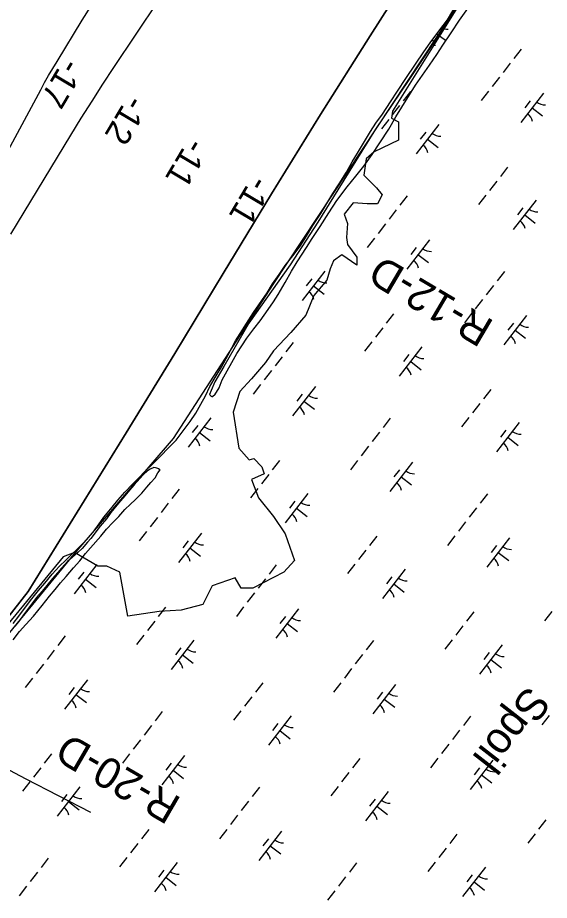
# Model space of a CAD drawing. Extents: x 3888273 to 3909528, y 158682 to 181032.
# Drawn here: x 3901510 to 3902228, y 169134 to 170326 of the extents above; entities that cross this region are included whole.
import ezdxf

# ---------------------------------------------------------------- set-up
doc = ezdxf.new("R2010")
doc.units = 0
for name, color, linetype in [('V-CHAN-SPOL', 7, 'Continuous'), ('V-LEVE-TOET', 7, 'Continuous'), ('V-RIVR-EDGE', 7, 'Continuous'), ('V-RIVR-JETY', 7, 'Continuous'), ('V-RIVR-RANG', 7, 'Continuous'), ('V-RIVR-RANG-IDEN', 7, 'Continuous'), ('V-RRAP-FSHR', 7, 'Continuous'), ('V-TOPO-DPTH', 7, 'Continuous'), ('V-TOPO-MINR', 7, 'Continuous'), ('V-WETL-SWMP', 7, 'Continuous')]:
    doc.layers.add(name, color=color, linetype=linetype)

msp = doc.modelspace()

# ---------------------------------------------------------------- linework, layer by layer
at = {"layer": 'V-LEVE-TOET'}
msp.add_lwpolyline([(3901608.3, 169252.6), (3901521, 169297.6), (3901468.7, 169325), (3901399.6, 169361.3), (3901370.6, 169378.6), (3901358, 169391.3)], dxfattribs=at)
at = {"layer": 'V-RIVR-EDGE'}
msp.add_lwpolyline([(3902103.9, 170339.9), (3902016.4, 170199.2), (3902014.9, 170189.8), (3902024.2, 170185.1), (3902024.2, 170160.1), (3901991.4, 170144.5), (3901980.5, 170135.1), (3901977.3, 170113.2), (3901994.5, 170096), (3902002.3, 170086.6), (3901996.1, 170074.1), (3901982, 170074.1), (3901963.3, 170075.7), (3901950.8, 170060.1), (3901955.5, 170047.6), (3901953.9, 170028.8), (3901955.5, 170019.4), (3901968, 170002.2), (3901968, 169991.3), (3901947.6, 170005.4), (3901936.7, 169997.5), (3901932, 169986.6), (3901927.3, 169971), (3901910.1, 169950.6), (3901899.2, 169924.1), (3901878.9, 169900.6), (3901855.4, 169875.6), (3901844.5, 169860), (3901825.7, 169838.1), (3901810.1, 169820.9), (3901800.7, 169792.8), (3901808.5, 169744.3), (3901822.6, 169728.7), (3901828.8, 169730.2), (3901839.8, 169719.3), (3901842.9, 169709.9), (3901825.7, 169702.1), (3901835.1, 169677.1), (3901855.4, 169652.1), (3901871, 169628.6), (3901883.6, 169592.7), (3901869.5, 169577.1), (3901827.3, 169555.2), (3901811.6, 169555.2), (3901803.8, 169569.3), (3901772.6, 169558.3), (3901760.1, 169533.3), (3901730.4, 169525.5), (3901700.7, 169523.9), (3901658.5, 169517.7), (3901647.5, 169577.1), (3901630.3, 169584.9), (3901617.8, 169584.9), (3901586.6, 169603.6), (3901570.9, 169597.4), (3901397.4, 169386.4)], dxfattribs=at)
at = {"layer": 'V-RIVR-JETY'}
for points in [[(3902102, 170336.8), (3902038.2, 170241.9), (3901993.1, 170175), (3901966.5, 170132.2), (3901942.3, 170093.4), (3901915.3, 170049.3), (3901877.7, 169991.7), (3901822.1, 169913.1), (3901788.1, 169854.7), (3901776, 169833.9)], [(3901785.9, 169836.8), (3901805.8, 169872.4), (3901819.5, 169892.8), (3901828.9, 169905.3), (3901837.6, 169916.1), (3901848.1, 169931.7), (3901855.2, 169942.1), (3901861.5, 169951.7), (3901871.2, 169968.1), (3901879.8, 169983.3), (3901887.2, 169995.8), (3901900.2, 170015.4), (3901907.6, 170027.4), (3901918.6, 170043.8), (3901930.3, 170062.2), (3901940.9, 170078.6), (3901955, 170097.1), (3901966.8, 170111.5), (3901977.3, 170125.1), (3901988.7, 170140.8), (3901999.3, 170156.8), (3902011.4, 170175.2), (3902020.8, 170191.6), (3902047.4, 170234.4), (3902066.2, 170261.3), (3902076, 170276.1), (3902084.2, 170288.5), (3902095.6, 170305.3), (3902106.9, 170322.2), (3902117.9, 170338.2)], [(3901776, 169833.9), (3901771, 169822.3), (3901769, 169816.8), (3901770.6, 169814.8), (3901770.6, 169814.4), (3901772.2, 169814), (3901773, 169814), (3901776.6, 169817.2), (3901778.5, 169820), (3901782, 169826), (3901785.9, 169836.8)], [(3901503.6, 169485.7), (3901512.2, 169496.9), (3901520.5, 169506.2), (3901531.1, 169517.4), (3901542.9, 169531.9), (3901552.7, 169544.3), (3901560.5, 169553.5), (3901567.6, 169562.3), (3901575.1, 169571.2), (3901584.9, 169582.8), (3901593.5, 169592.4), (3901601.4, 169602.1), (3901608.1, 169609.7), (3901621.8, 169625.7), (3901629.7, 169635), (3901638.3, 169644.2), (3901646.2, 169652.2), (3901654.4, 169661.5), (3901662.3, 169668.7), (3901668.6, 169674.7), (3901677.3, 169683.6), (3901684.3, 169691.6), (3901689.4, 169698), (3901695.3, 169704.5), (3901699.2, 169710.9), (3901702, 169714.9), (3901702, 169714.9), (3901700.8, 169715.6), (3901700.8, 169716.4), (3901699.2, 169716.8), (3901697.6, 169717.2), (3901696, 169717.6), (3901693.6, 169718.4), (3901688.5, 169715.9), (3901684.9, 169713.9), (3901679.8, 169708.7), (3901674.7, 169703.4), (3901667.2, 169695), (3901660.9, 169687.8), (3901654.6, 169679.8), (3901646, 169670.1), (3901635.4, 169657.7), (3901629.5, 169648.9), (3901621.3, 169638.9), (3901608.7, 169622.4), (3901604, 169617.2), (3901596.9, 169608.8), (3901591, 169603.5), (3901583.5, 169597.1), (3901576.8, 169591.1), (3901569, 169582.2), (3901563.9, 169576.6), (3901556.8, 169568.2), (3901548.9, 169559), (3901542.7, 169551.3), (3901535.2, 169542.5), (3901526.9, 169532.1), (3901518.7, 169520.9), (3901510.9, 169510), (3901506.2, 169504.4)]]:
    msp.add_lwpolyline(points, dxfattribs=at)
at = {"layer": 'V-RRAP-FSHR'}
msp.add_lwpolyline([(3899996.7, 166588.8), (3900029.7, 166643.4), (3900051.8, 166695.8), (3900145, 166878), (3900473, 167514.6), (3900528.8, 167603.3), (3900571.9, 167693.2), (3900769.5, 168220.1), (3900854, 168410.1), (3901111.7, 168921.3), (3901230.8, 169130.1), (3901232.3, 169133), (3901298.6, 169231.8), (3901395, 169369.5), (3901586, 169601.1), (3901720.2, 169757.4), (3901855.1, 169965.2), (3902076, 170299.4), (3902258.6, 170576), (3902394.3, 170771.7), (3902466.4, 170877.4)], dxfattribs=at)
at = {"layer": 'V-TOPO-DPTH'}
for points in [[(3902745.9, 171376.6), (3902701.4, 171321.5), (3902669.5, 171281.6), (3902638.1, 171241.4), (3902607.1, 171200.8), (3902576.5, 171159.9), (3902314.2, 170804.4), (3902294.8, 170777.6), (3902275.9, 170750.7), (3902257.4, 170723.3), (3902239.3, 170695.8), (3902053.6, 170407.4), (3901985.9, 170301.2), (3901918.9, 170194.7), (3901852.7, 170087.6), (3901787.2, 169980.1), (3901721.9, 169872.4), (3901656.3, 169765), (3901590.2, 169657.8), (3901523.7, 169550.8), (3901139.1, 169059.9)], [(3901467.8, 170093.5), (3901540.7, 170228.2), (3901546, 170237.9), (3901551.5, 170247.5), (3901557.1, 170257.1), (3901562.8, 170266.6), (3901597, 170322.5), (3901620.1, 170359.8)], [(3901467.8, 170093.5), (3901540.7, 170228.2), (3901546, 170237.9), (3901551.5, 170247.5), (3901557.1, 170257.1), (3901562.8, 170266.6), (3901597, 170322.5), (3901620.1, 170359.8)]]:
    msp.add_lwpolyline(points, dxfattribs=at)
at = {"layer": 'V-TOPO-MINR'}
for points in [[(3901500.4, 170033.5), (3901581.3, 170166.8), (3901595.6, 170189.9), (3901610.1, 170212.9), (3901624.9, 170235.7), (3901639.8, 170258.4), (3901700, 170348.3), (3901745, 170416), (3901789.9, 170483.7), (3901834.4, 170551.7), (3901878.7, 170619.9), (3902010, 170822.7), (3902029.6, 170853.2), (3902049.2, 170883.7), (3902068.6, 170914.2), (3902088, 170944.8), (3902503.4, 171603.5), (3902912.5, 172181.4)], [(3901139.1, 169059.9), (3901523.7, 169550.8), (3901590.2, 169657.8), (3901656.3, 169765), (3901721.9, 169872.4), (3901787.2, 169980.1), (3901852.7, 170087.6), (3901918.9, 170194.7), (3901985.9, 170301.2), (3902053.6, 170407.4), (3902239.3, 170695.8), (3902257.4, 170723.3), (3902275.9, 170750.7), (3902294.8, 170777.6), (3902314.2, 170804.4), (3902576.5, 171159.9), (3902607.1, 171200.8), (3902638.1, 171241.4), (3902669.5, 171281.6), (3902701.4, 171321.5), (3902745.9, 171376.6)], [(3901467.8, 170093.5), (3901540.7, 170228.2), (3901546, 170237.9), (3901551.5, 170247.5), (3901557.1, 170257.1), (3901562.8, 170266.6), (3901597, 170322.5), (3901620.1, 170359.8)]]:
    msp.add_lwpolyline(points, dxfattribs=at)
at = {"layer": 'V-WETL-SWMP'}
for p, q in [((3902090.5, 170322.9), (3902102.4, 170342.6)), ((3902078.9, 170307.5), (3902090.5, 170322.9)), ((3902067.3, 170291.7), (3902078.9, 170307.5)), ((3902076.3, 170304), (3902087.8, 170295.1)), ((3902058.8, 170279.5), (3902067.3, 170291.7)), ((3902047.3, 170262.9), (3902058.8, 170279.5)), ((3902190.3, 170283), (3902180.4, 170270.4)), ((3902175.5, 170264.1), (3902165.7, 170251.4)), ((3902034.1, 170243.6), (3902047.3, 170262.9)), ((3902023, 170226.6), (3902034.1, 170243.6)), ((3902160.8, 170245.1), (3902151, 170232.5)), ((3902013.7, 170212.1), (3902023, 170226.6)), ((3902040.6, 170225.9), (3902030.8, 170213.3)), ((3902146, 170226.2), (3902136.2, 170213.6)), ((3902220.2, 170223.7), (3902189.5, 170184.3)), ((3902002.5, 170195.5), (3902013.7, 170212.1)), ((3902025.8, 170207), (3902016, 170194.4)), ((3902202.4, 170213.5), (3902195.1, 170204)), ((3902204.8, 170204), (3902219, 170192.9)), ((3901993.6, 170183.2), (3902002.5, 170195.5)), ((3901986.7, 170171.8), (3901993.6, 170183.2)), ((3902011.1, 170188.1), (3902001.3, 170175.4)), ((3902078.9, 170181.3), (3902048.2, 170141.8)), ((3901978.6, 170158.4), (3901986.7, 170171.8)), ((3902061.2, 170171), (3902053.8, 170161.5)), ((3901969, 170142.6), (3901978.6, 170158.4)), ((3902063.6, 170161.5), (3902077.8, 170150.5)), ((3901961.7, 170131.2), (3901969, 170142.6)), ((3901954, 170117), (3901961.7, 170131.2)), ((3902171.9, 170123.8), (3902162, 170111.2)), ((3901944, 170101.3), (3901954, 170117)), ((3901935.5, 170088.2), (3901944, 170101.3)), ((3902157.1, 170104.9), (3902147.3, 170092.2)), ((3901929, 170076.8), (3901935.5, 170088.2)), ((3902036.2, 170085), (3902026.3, 170072.3)), ((3902142.4, 170085.9), (3902132.6, 170073.3)), ((3901919.3, 170061), (3901929, 170076.8)), ((3902210.2, 170079.1), (3902179.5, 170039.7)), ((3901908.5, 170044.9), (3901919.3, 170061)), ((3902021.4, 170066), (3902011.6, 170053.4)), ((3902192.5, 170068.9), (3902185.1, 170059.4)), ((3902194.9, 170059.4), (3902209.1, 170048.3)), ((3901900.1, 170030.7), (3901908.5, 170044.9)), ((3902006.7, 170047.1), (3901996.9, 170034.4)), ((3901891.6, 170017.3), (3901900.1, 170030.7)), ((3901991.9, 170028.1), (3901982.1, 170015.5)), ((3902066.1, 170025.7), (3902035.4, 169986.2)), ((3901881.5, 170004.2), (3901891.6, 170017.3)), ((3902048.3, 170015.4), (3902041, 170005.9)), ((3901871.1, 169990.8), (3901881.5, 170004.2)), ((3902050.7, 170005.9), (3902064.9, 169994.9)), ((3901863, 169979), (3901871.1, 169990.8)), ((3901854.1, 169966.4), (3901863, 169979)), ((3901924.8, 169983.2), (3901894.1, 169943.7)), ((3902167.4, 169982.8), (3902157.6, 169970.2)), ((3901846.8, 169954.1), (3901854.1, 169966.4)), ((3901907.1, 169972.9), (3901899.7, 169963.5)), ((3901828.3, 169927.7), (3901846.8, 169954.1)), ((3901909.5, 169963.5), (3901923.7, 169952.4)), ((3902152.7, 169963.9), (3902142.9, 169951.2)), ((3902138, 169944.9), (3902128.1, 169932.3)), ((3901804, 169889.5), (3901828.3, 169927.7)), ((3902017.8, 169925.7), (3902007.9, 169913.1)), ((3902123.2, 169926), (3902113.4, 169913.4)), ((3902197.4, 169923.5), (3902166.7, 169884)), ((3902003, 169906.8), (3901993.2, 169894.2)), ((3902179.6, 169913.2), (3902172.2, 169903.8)), ((3902182, 169903.8), (3902196.2, 169892.7)), ((3901794, 169870.2), (3901804, 169889.5)), ((3901882, 169886.9), (3901872.2, 169874.3)), ((3901988.3, 169887.9), (3901978.5, 169875.2)), ((3901785.6, 169854.8), (3901794, 169870.2)), ((3902056.1, 169881.1), (3902025.4, 169841.6)), ((3902038.4, 169870.8), (3902031, 169861.3)), ((3901867.3, 169867.9), (3901857.5, 169855.3)), ((3902040.8, 169861.3), (3902055, 169850.3)), ((3901777.9, 169841.8), (3901785.6, 169854.8)), ((3901852.6, 169849), (3901842.7, 169836.4)), ((3901769.4, 169827.6), (3901777.9, 169841.8)), ((3901763.3, 169815), (3901769.4, 169827.6)), ((3901837.8, 169830.1), (3901828, 169817.4)), ((3901912, 169827.6), (3901881.3, 169788.1)), ((3902149, 169823.6), (3902139.2, 169811)), ((3901757.1, 169803.6), (3901763.3, 169815)), ((3901894.2, 169817.3), (3901886.9, 169807.9)), ((3901750.6, 169791.4), (3901757.1, 169803.6)), ((3901896.6, 169807.9), (3901910.8, 169796.8)), ((3902134.3, 169804.7), (3902124.5, 169792)), ((3901742.9, 169780.3), (3901750.6, 169791.4)), ((3901724, 169755), (3901742.9, 169780.3)), ((3901770.7, 169785.1), (3901740, 169745.7)), ((3901753, 169774.9), (3901745.6, 169765.4)), ((3902013.3, 169784.7), (3902003.5, 169772.1)), ((3902119.6, 169785.7), (3902109.7, 169773.1)), ((3902187.4, 169778.9), (3902156.7, 169739.5)), ((3901755.4, 169765.4), (3901769.6, 169754.4)), ((3901998.6, 169765.8), (3901988.8, 169753.2)), ((3902169.6, 169768.7), (3902162.3, 169759.2)), ((3901692.2, 169723.4), (3901724, 169755)), ((3902172.1, 169759.2), (3902186.3, 169748.1)), ((3901983.9, 169746.9), (3901974, 169734.2)), ((3901863.7, 169727.7), (3901853.8, 169715)), ((3901969.1, 169727.9), (3901959.3, 169715.3)), ((3901682.1, 169713.5), (3901692.2, 169723.4)), ((3902043.3, 169725.4), (3902012.6, 169686)), ((3902025.5, 169715.2), (3902018.1, 169705.7)), ((3901664.7, 169695.7), (3901672.4, 169703.2)), ((3901672.4, 169703.2), (3901682.1, 169713.5)), ((3901848.9, 169708.7), (3901839.1, 169696.1)), ((3902027.9, 169705.7), (3902042.1, 169694.7)), ((3901654.6, 169685), (3901664.7, 169695.7)), ((3901644.9, 169674.3), (3901654.6, 169685)), ((3901727.9, 169688.8), (3901718.1, 169676.2)), ((3901834.2, 169689.8), (3901824.4, 169677.2)), ((3901902, 169683), (3901871.3, 169643.5)), ((3902144.6, 169682.6), (3902134.8, 169670)), ((3901637.2, 169664.8), (3901644.9, 169674.3)), ((3901713.2, 169669.9), (3901703.4, 169657.3)), ((3901884.3, 169672.7), (3901876.9, 169663.3)), ((3901626, 169651), (3901637.2, 169664.8)), ((3901886.7, 169663.3), (3901900.9, 169652.2)), ((3902129.9, 169663.7), (3902120, 169651)), ((3901619.8, 169642.3), (3901626, 169651)), ((3901698.5, 169650.9), (3901688.6, 169638.3)), ((3902115.1, 169644.7), (3902105.3, 169632.1)), ((3901611.7, 169630.9), (3901619.8, 169642.3)), ((3901683.7, 169632), (3901673.9, 169619.4)), ((3901591.5, 169609.1), (3901602.4, 169620.2)), ((3901602.4, 169620.2), (3901611.7, 169630.9)), ((3901757.9, 169629.5), (3901727.2, 169590.1)), ((3901994.9, 169625.5), (3901985.1, 169612.9)), ((3902100.4, 169625.8), (3902090.6, 169613.1)), ((3902174.5, 169623.3), (3902143.8, 169583.8)), ((3901581.1, 169599.2), (3901591.5, 169609.1)), ((3901740.1, 169619.3), (3901732.7, 169609.8)), ((3901742.5, 169609.8), (3901756.7, 169598.7)), ((3902156.8, 169613), (3902149.4, 169603.6)), ((3901574.5, 169592.9), (3901581.1, 169599.2)), ((3901980.2, 169606.6), (3901970.4, 169594)), ((3902159.2, 169603.6), (3902173.4, 169592.5)), ((3901556.3, 169574.3), (3901566.3, 169585)), ((3901566.3, 169585), (3901574.5, 169592.9)), ((3901616.6, 169587.1), (3901585.9, 169547.6)), ((3901859.2, 169586.7), (3901849.4, 169574.1)), ((3901965.5, 169587.6), (3901955.6, 169575)), ((3901546.2, 169562), (3901556.3, 169574.3)), ((3901598.9, 169576.8), (3901591.5, 169567.3)), ((3902033.3, 169580.9), (3902002.6, 169541.4)), ((3901537.7, 169552.2), (3901546.2, 169562)), ((3901601.3, 169567.3), (3901615.5, 169556.3)), ((3901844.5, 169567.7), (3901834.7, 169555.1)), ((3902015.5, 169570.6), (3902008.2, 169561.1)), ((3902017.9, 169561.1), (3902032.2, 169550.1)), ((3901528.8, 169541.1), (3901537.7, 169552.2)), ((3901829.7, 169548.8), (3901819.9, 169536.2)), ((3901520.3, 169529.6), (3901528.8, 169541.1)), ((3901511, 169517.4), (3901520.3, 169529.6)), ((3901709.5, 169529.6), (3901699.7, 169517)), ((3901815, 169529.9), (3901805.2, 169517.2)), ((3901889.2, 169527.4), (3901858.4, 169487.9)), ((3901503.3, 169507.5), (3901511, 169517.4)), ((3901871.4, 169517.1), (3901864, 169507.7)), ((3902126.2, 169523.4), (3902116.4, 169510.8)), ((3902231.7, 169523.6), (3902221.9, 169511)), ((3901694.8, 169510.7), (3901685, 169498)), ((3901873.8, 169507.6), (3901888, 169496.6)), ((3902111.5, 169504.4), (3902101.7, 169491.8)), ((3901573.8, 169490.8), (3901564, 169478.1)), ((3901680.1, 169491.7), (3901670.2, 169479.1)), ((3901747.9, 169484.9), (3901717.2, 169445.5)), ((3901990.5, 169484.5), (3901980.7, 169471.9)), ((3902096.7, 169485.5), (3902086.9, 169472.9)), ((3902164.6, 169478.7), (3902133.9, 169439.2)), ((3901559.1, 169471.8), (3901549.3, 169459.2)), ((3901730.2, 169474.7), (3901722.8, 169465.2)), ((3901732.6, 169465.2), (3901746.8, 169454.1)), ((3901975.8, 169465.6), (3901965.9, 169453)), ((3902146.8, 169468.4), (3902139.5, 169459)), ((3901544.4, 169452.9), (3901534.5, 169440.2)), ((3902149.2, 169459), (3902163.4, 169447.9)), ((3901961, 169446.7), (3901951.2, 169434)), ((3901529.6, 169433.9), (3901519.8, 169421.3)), ((3901603.8, 169431.5), (3901573.1, 169392)), ((3901586, 169421.2), (3901578.6, 169411.7)), ((3901840.8, 169427.5), (3901831, 169414.8)), ((3901946.3, 169427.7), (3901936.5, 169415.1)), ((3902020.4, 169425.2), (3901989.7, 169385.8)), ((3901588.4, 169411.7), (3901602.6, 169400.7)), ((3901826.1, 169408.5), (3901816.3, 169395.9)), ((3902002.7, 169415), (3901995.3, 169405.5)), ((3902005.1, 169405.5), (3902019.3, 169394.5)), ((3901705.1, 169388.6), (3901695.3, 169376)), ((3901811.4, 169389.6), (3901801.5, 169377)), ((3901879.2, 169382.8), (3901848.5, 169343.3)), ((3902121.8, 169382.4), (3902112, 169369.8)), ((3902228, 169383.4), (3902218.2, 169370.7)), ((3901690.4, 169369.7), (3901680.6, 169357)), ((3901861.4, 169372.5), (3901854.1, 169363.1)), ((3901863.8, 169363.1), (3901878, 169352)), ((3902107, 169363.4), (3902097.2, 169350.8)), ((3901675.6, 169350.7), (3901665.8, 169338.1)), ((3902092.3, 169344.5), (3902082.5, 169331.9)), ((3901555.4, 169331.5), (3901545.6, 169318.9)), ((3901660.9, 169331.8), (3901651.1, 169319.2)), ((3901735, 169329.3), (3901704.3, 169289.9)), ((3901972.1, 169325.3), (3901962.3, 169312.7)), ((3902077.6, 169325.6), (3902067.7, 169312.9)), ((3902151.7, 169323.1), (3902121, 169283.6)), ((3901540.7, 169312.6), (3901530.9, 169300)), ((3901717.3, 169319.1), (3901709.9, 169309.6)), ((3901719.7, 169309.6), (3901733.9, 169298.5)), ((3902134, 169312.8), (3902126.6, 169303.4)), ((3901957.4, 169306.4), (3901947.5, 169293.8)), ((3902136.4, 169303.4), (3902150.6, 169292.3)), ((3901526, 169293.7), (3901516.1, 169281)), ((3901593.8, 169286.9), (3901563.1, 169247.4)), ((3901836.4, 169286.5), (3901826.6, 169273.8)), ((3901942.6, 169287.4), (3901932.8, 169274.8)), ((3901576, 169276.6), (3901568.7, 169267.1)), ((3902010.5, 169280.6), (3901979.8, 169241.2)), ((3901578.5, 169267.1), (3901592.7, 169256.1)), ((3901821.7, 169267.5), (3901811.8, 169254.9)), ((3901992.7, 169270.4), (3901985.3, 169260.9)), ((3901995.1, 169260.9), (3902009.3, 169249.9)), ((3901806.9, 169248.6), (3901797.1, 169236)), ((3902223.6, 169242.4), (3902213.8, 169229.7)), ((3901686.7, 169229.4), (3901676.9, 169216.8)), ((3901792.2, 169229.6), (3901782.4, 169217)), ((3901866.3, 169227.2), (3901835.6, 169187.7)), ((3901848.6, 169216.9), (3901841.2, 169207.4)), ((3902103.4, 169223.2), (3902093.6, 169210.5)), ((3902208.9, 169223.4), (3902199, 169210.8)), ((3901672, 169210.5), (3901662.2, 169197.8)), ((3901851, 169207.4), (3901865.2, 169196.4)), ((3902088.7, 169204.2), (3902078.8, 169191.6)), ((3901551, 169190.6), (3901541.2, 169177.9)), ((3901657.2, 169191.5), (3901647.4, 169178.9)), ((3901725.1, 169184.7), (3901694.4, 169145.3)), ((3901967.7, 169184.3), (3901957.9, 169171.7)), ((3902073.9, 169185.3), (3902064.1, 169172.7)), ((3902141.8, 169178.5), (3902111, 169139)), ((3901536.3, 169171.6), (3901526.4, 169159)), ((3901707.3, 169174.5), (3901700, 169165)), ((3902124, 169168.2), (3902116.6, 169158.8)), ((3901709.7, 169165), (3901723.9, 169153.9)), ((3901952.9, 169165.4), (3901943.1, 169152.8)), ((3902126.4, 169158.8), (3902140.6, 169147.7)), ((3901521.5, 169152.7), (3901511.7, 169140)), ((3901938.2, 169146.4), (3901928.4, 169133.8))]:
    msp.add_line(p, q, dxfattribs=at)
for centre, start, end in [((3902090.7, 170327.8), 242.0233, 272.8866), ((3902056.8, 170284.2), 11.343, 40.5183), ((3902222, 170225.6), 231.343, 272.8866), ((3902188.1, 170182), 11.343, 52.8866), ((3902080.7, 170183.2), 231.343, 272.8866), ((3902046.8, 170139.6), 11.343, 52.8866), ((3902212, 170081), 231.343, 272.8866), ((3902178.1, 170037.4), 11.343, 52.8866), ((3902067.9, 170027.6), 231.343, 272.8866), ((3902034, 169984), 11.343, 52.8866), ((3901926.6, 169985.1), 231.343, 272.8866), ((3901892.7, 169941.5), 11.343, 52.8866), ((3902199.2, 169925.4), 231.343, 272.8866), ((3902165.2, 169881.8), 11.343, 52.8866), ((3902057.9, 169883), 231.343, 272.8866), ((3902024, 169839.4), 11.343, 52.8866), ((3901913.8, 169829.5), 231.343, 272.8866), ((3901879.9, 169785.9), 11.343, 52.8866), ((3901772.5, 169787.1), 231.343, 272.8866), ((3902189.2, 169780.8), 231.343, 272.8866), ((3901738.6, 169743.5), 11.343, 52.8866), ((3902155.3, 169737.2), 11.343, 52.8866), ((3902045.1, 169727.4), 231.343, 272.8866), ((3902011.1, 169683.8), 11.343, 52.8866), ((3901903.8, 169684.9), 231.343, 272.8866), ((3901869.9, 169641.3), 11.343, 52.8866), ((3901759.7, 169631.4), 231.343, 272.8866), ((3902176.3, 169625.2), 231.343, 272.8866), ((3901725.7, 169587.8), 11.343, 52.8866), ((3902142.4, 169581.6), 11.343, 52.8866), ((3901618.4, 169589), 231.343, 272.8866), ((3902035.1, 169582.8), 231.343, 272.8866), ((3901584.5, 169545.4), 11.343, 52.8866), ((3902001.2, 169539.2), 11.343, 52.8866), ((3901891, 169529.3), 231.343, 272.8866), ((3901857, 169485.7), 11.343, 52.8866), ((3901749.7, 169486.9), 231.343, 272.8866), ((3902166.4, 169480.6), 231.343, 272.8866), ((3901715.8, 169443.3), 11.343, 52.8866), ((3902132.5, 169437), 11.343, 52.8866), ((3901605.6, 169433.4), 231.343, 272.8866), ((3902022.2, 169427.2), 231.343, 272.8866), ((3901571.6, 169389.8), 11.343, 52.8866), ((3901988.3, 169383.6), 11.343, 52.8866), ((3901881, 169384.7), 231.343, 272.8866), ((3901847.1, 169341.1), 11.343, 52.8866), ((3901736.8, 169331.2), 231.343, 272.8866), ((3902153.5, 169325), 231.343, 272.8866), ((3901702.9, 169287.6), 11.343, 52.8866), ((3902119.6, 169281.4), 11.343, 52.8866), ((3901595.6, 169288.8), 231.343, 272.8866), ((3902012.3, 169282.6), 231.343, 272.8866), ((3901561.7, 169245.2), 11.343, 52.8866), ((3901978.3, 169239), 11.343, 52.8866), ((3901868.1, 169229.1), 231.343, 272.8866), ((3901834.2, 169185.5), 11.343, 52.8866), ((3901726.9, 169186.6), 231.343, 272.8866), ((3902143.6, 169180.4), 231.343, 272.8866), ((3901693, 169143), 11.343, 52.8866), ((3902109.6, 169136.8), 11.343, 52.8866)]:
    msp.add_arc(centre, 17.6, start, end, dxfattribs=at)

# ---------------------------------------------------------------- texts
at = {"layer": 'V-CHAN-SPOL'}
msp.add_text('Spoil', height=42, rotation=232.1185, dxfattribs=at).set_placement((3902199.3, 169425.5))
at = {"layer": 'V-RIVR-RANG'}
for s, p in [('-17', (3901572.4, 170272.8)), ('-12', (3901659.2, 170223.1)), ('-11', (3901741.1, 170165.1)), ('-11', (3901827.2, 170114.3))]:
    msp.add_text(s, height=33.5, rotation=239.3083, dxfattribs=at).set_placement(p)
at = {"layer": 'V-RIVR-RANG-IDEN'}
for s, rotation, p in [('R-12-D', 149.4465, (3902155.2, 169915.1)), ('R-20-D', 149.8399, (3901732.5, 169270.9))]:
    msp.add_text(s, height=41.5, rotation=rotation, dxfattribs=at).set_placement(p)

doc.saveas('drawing.dxf')
